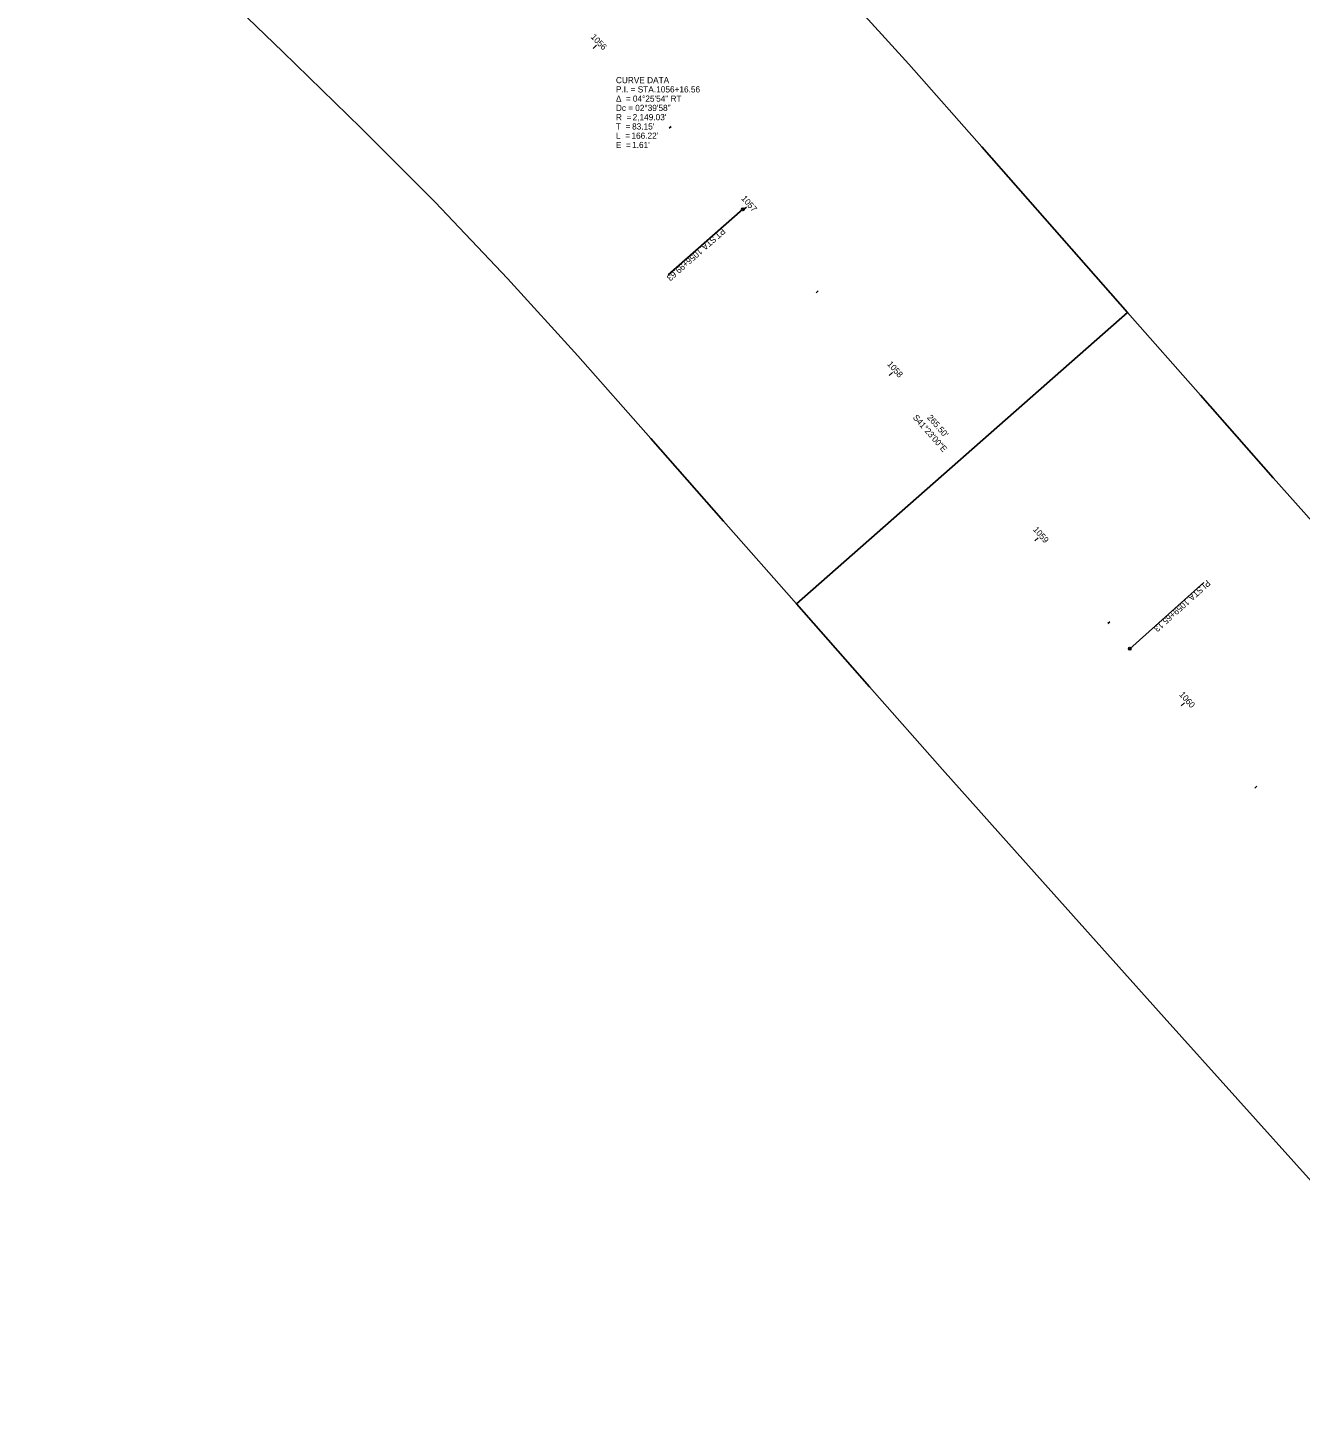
# Model space of a CAD drawing. Extents: x 1846275 to 1850613, y 577927 to 582526.
# Drawn here: x 1847638 to 1848215, y 580235 to 580870 of the extents above; entities that cross this region are included whole.
import ezdxf

# ---------------------------------------------------------------- set-up
doc = ezdxf.new("R2010")
doc.units = 0
for name, color, linetype in [('GE_P_Alignment_100_Cardinal_Points', 7, 'Continuous'), ('PM_P_Cells', 7, 'Continuous'), ('PM_P_Stop_Line', 7, 'Continuous'), ('PM_P_Transverse_Line', 7, 'Continuous'), ('SH_Named_Boundary', 7, 'Continuous'), ('XS_P_Pavt_Surface', 7, 'Continuous')]:
    doc.layers.add(name, color=color, linetype=linetype)

msp = doc.modelspace()

# ---------------------------------------------------------------- linework, layer by layer
at = {"layer": 'GE_P_Alignment_100_Cardinal_Points'}
for p, q in [((1847894.13, 580860.41), (1847895.56, 580861.8)), ((1847928.58, 580824.18), (1847929.46, 580825)), ((1847962.19, 580787.16), (1847963.69, 580788.48)), ((1847995.24, 580749.64), (1847996.14, 580750.43)), ((1848028.29, 580712.13), (1848029.8, 580713.45)), ((1848061.35, 580674.61), (1848062.25, 580675.4)), ((1848094.4, 580637.1), (1848095.9, 580638.42)), ((1848127.46, 580599.58), (1848128.36, 580600.37)), ((1848160.74, 580562.26), (1848162.22, 580563.6)), ((1848194.11, 580525.03), (1848195, 580525.83))]:
    msp.add_line(p, q, dxfattribs=at)
at = {"layer": 'PM_P_Cells'}
for p, q in [((1847961.94, 580787.43), (1847928.18, 580757.69)), ((1848137.46, 580588.23), (1848170.97, 580618.26))]:
    msp.add_line(p, q, dxfattribs=at)
for centre in [(1847961.94, 580787.43), (1848137.46, 580588.23)]:
    msp.add_circle(centre, 0.6, dxfattribs=at)
at = {"layer": 'SH_Named_Boundary'}
for points in [[(1847804.3, 581095.73), (1847637.89, 580984.79), (1847677.25, 580934.02), (1847717.47, 580893.57), (1847753.39, 580858.79), (1847788.83, 580824.42), (1847822.47, 580790.65), (1847855.33, 580756.11), (1847887.16, 580721.04), (1847920.21, 580683.53), (1847953.27, 580646.01), (1847986.32, 580608.49), (1848136.39, 580740.71), (1848103.33, 580778.23), (1848070.28, 580815.74), (1848037.22, 580853.26), (1848001.85, 580892.24), (1847965.79, 580930.16), (1847928.86, 580967.22), (1847892.51, 581002.48), (1847856.59, 581037.26), (1847826.16, 581067.54)], [(1848136.39, 580740.71), (1847986.32, 580608.49), (1848019.38, 580570.98), (1848052.43, 580533.46), (1848086.28, 580495.51), (1848119.65, 580458.28), (1848153.02, 580421.04), (1848186.4, 580383.81), (1848219.77, 580346.58), (1848253.14, 580309.35), (1848286.52, 580272.12), (1848319.89, 580234.88), (1848468.82, 580368.38), (1848435.45, 580405.61), (1848402.07, 580442.84), (1848368.7, 580480.07), (1848335.33, 580517.31), (1848301.95, 580554.54), (1848268.58, 580591.77), (1848235.21, 580629), (1848202.49, 580665.68), (1848169.44, 580703.2)]]:
    msp.add_lwpolyline(points, close=True, dxfattribs=at)

# ---------------------------------------------------------------- texts
at = {"layer": 'GE_P_Alignment_100_Cardinal_Points'}
for s, rotation, p in [('1056', 314.22858, (1847892.8, 580865.36)), ('1057', 311.38333, (1847961.06, 580792.21)), ('1058', 311.38333, (1848027.23, 580717.12)), ('1059', 311.38333, (1848093.35, 580642.08)), ('1060', 311.8718, (1848159.62, 580567.26))]:
    msp.add_text(s, height=2.8, rotation=rotation, dxfattribs=at).set_placement(p)
at = {"layer": 'PM_P_Cells'}
for s, rotation, p in [(' STA. ', 221.38333, (1847949.24, 580776.19)), ('PT', 221.38333, (1847952.55, 580779.1)), ('1056+99.63', 221.38333, (1847942.15, 580769.94)), (' STA. ', 221.8718, (1848169.91, 580617.26)), ('PI', 221.8718, (1848172.44, 580619.53)), ('1059+65.13', 221.8718, (1848162.88, 580610.95))]:
    msp.add_text(s, height=2.8, rotation=rotation, dxfattribs=at).set_placement(p)
at = {"layer": 'PM_P_Stop_Line'}
msp.add_text('S41°23\'00"E', height=2.8, rotation=311.38333, dxfattribs=at).set_placement((1848038.87, 580692.87))
at = {"layer": 'PM_P_Transverse_Line'}
for s, p in [('CURVE DATA', (1847904.44, 580844.62)), ('Δ  = ', (1847904.44, 580836.22)), ('P.I. = STA. ', (1847904.44, 580840.42)), ('04°25\'54" RT', (1847912.12, 580836.22)), ('1056+16.56', (1847922.71, 580840.42)), ('Dc = ', (1847904.44, 580832.02)), ('02°39\'58"', (1847913.18, 580832.02)), ('T  = ', (1847904.44, 580823.62)), ('R  = ', (1847904.44, 580827.82)), ("83.15'", (1847911.78, 580823.62)), ("2,149.03'", (1847912.02, 580827.82)), ('L  = ', (1847904.44, 580819.42)), ("166.22'", (1847911.48, 580819.42)), ('E  = ', (1847904.44, 580815.22)), ("1.61'", (1847911.78, 580815.22))]:
    msp.add_text(s, height=2.8, dxfattribs=at).set_placement(p)
at = {"layer": 'XS_P_Pavt_Surface'}
msp.add_text("265.50'", height=2.8, rotation=311.38333, dxfattribs=at).set_placement((1848045.32, 580692.87))

doc.saveas('drawing.dxf')
